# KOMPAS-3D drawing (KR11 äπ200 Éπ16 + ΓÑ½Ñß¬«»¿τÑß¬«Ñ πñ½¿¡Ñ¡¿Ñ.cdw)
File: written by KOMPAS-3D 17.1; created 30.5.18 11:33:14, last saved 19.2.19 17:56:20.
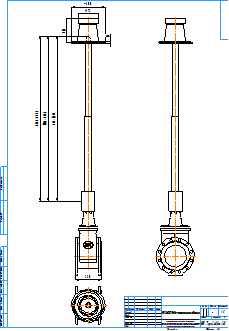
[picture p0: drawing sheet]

Sheet 1: A2, portrait

Title block, sheet 1: name: KR11 Ду200 Ру16 + телескопическое удлинение; sheets: 1; sheet format: A2; stored path: C:\Users\kka\KOMPAS_Work\!Trash\ГРАНАР KR Задвижки с приводами и удлинениями\С удлинениями\KR11 Ду150 Ру16 + телескопическое удлинение.cdw

Views: Вид 1, Проекционный вид 2, Проекционный вид 3
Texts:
  kka
  adl
  Рама для чертежей
  Лит-Масса-Масштаб
  Материал-Предприятие
  Масштаб
  Изм.
  Лист
  № докум.
  Подп.
  Дата
  Лит.
  Разраб.
  Пров.
  Т.контр.
  Листов
  Внимание! Данный продукт является объектом авторского права ООО «Торговый Дом АДЛ».
  Запрещается изменение, копирование, распространение
  (в том числе путем копирования на другие сайты и ресурсы в Интернете)
  или любое иное использование информации и объектов без предварительного
  согласия правообладателя (ООО «Торговый Дом АДЛ»).
  Н.контр.
  Утв.
  ООО "Торговый дом АДЛ"
  Изменение
  Номер документа
  Подпись
  Обозначение документа
  Наименование изделия
  Масса изделия по ГОСТ 2.109-73
  Порядковый номер листа
  Общее количество листов в документе
  Характер работы, выполненной лицом, подписавшим документ
  Наименование или индекс предприятия, выпускающего документ
  Инв. № подл.
  Подп. и дата
  Взам. инв. №
  Инв. № дубл.
  Инвентарный номер подлинника по ГОСТ 2.501-68
  Подпись принявшего подлинник в отдел технической документации
  Инвентарный номер подлинника, взамен которого выпущен данный подлинник
  Инвентарный номер дубликата по ГОСТ 2.502-68
  Подпись принявшего дубликат в отдел технической документации
  Справ. №
  Перв. примен.
  Обозначение документа, взамен или на основании которого выпущен данный документ
  Обозначение документа, в котором впервые записан данный документ
  Подпись лица, копировавшего чертеж
  Обозначение формата листа
  !Рама для чертежа
Dimensions and other numbers on the sheet: 853-; 1478; 1134-2034; 2000-3600; 300; 18; 210; 175; 230; 1:5; 1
